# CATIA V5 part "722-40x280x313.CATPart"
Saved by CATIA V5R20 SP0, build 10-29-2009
Part number: 722-40x280x313
Definition: NONE
Nomenclature: 722-40x280x313
Source: Unknown
Description: 722-40x280x313
Bounding box of the stored display mesh (mm): x -20 to 20, y -20 to 20, z -265 to 48
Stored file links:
  C:\Users\Utente\Desktop\IO LAVORO\3D X SITO CF\X SITO\722\722-40x280x313.CATPart
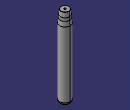
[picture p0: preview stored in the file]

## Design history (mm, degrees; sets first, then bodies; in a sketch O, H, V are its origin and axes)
Body1 "722-40x280x313" (main body)
  Solid1: solid without history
